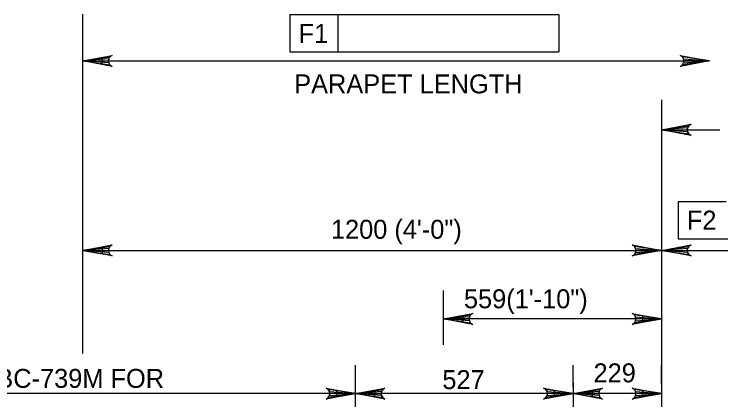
# Model space of a CAD drawing. Extents: x 0 to 36.3, y -66 to 0.
# Drawn here: x 4.419 to 8.89, y -11.865 to -9.424 of the extents above; entities that cross this region are included whole.
import ezdxf

# ---------------------------------------------------------------- set-up
doc = ezdxf.new("R2010")
doc.units = 0
doc.layers.add('3', color=7, linetype='Continuous')

msp = doc.modelspace()

# ---------------------------------------------------------------- linework, layer by layer
at = {"layer": '3'}
for p, q in [((4.8531, -11.5721), (4.8531, -9.4241)), ((6.1642, -9.4254), (6.4666, -9.4254)), ((6.1642, -9.4254), (6.1642, -9.6617)), ((6.4666, -9.4254), (6.4666, -9.6617)), ((6.4666, -9.4254), (7.8649, -9.4254)), ((7.8649, -9.4254), (7.8649, -9.6617)), ((6.1642, -9.6617), (7.8649, -9.6617)), ((4.8531, -9.72), (8.8184, -9.72)), ((8.5148, -9.9667), (8.5148, -16.3403)), ((8.5148, -10.1561), (8.8836, -10.1561)), ((8.6203, -10.6093), (8.9227, -10.6093)), ((8.6203, -10.6093), (8.6203, -10.8455)), ((8.6203, -10.8455), (10.0156, -10.8455)), ((4.8531, -10.9191), (8.5148, -10.9191)), ((8.5148, -10.9191), (13.045, -10.9191)), ((7.1347, -11.5162), (7.1347, -11.1725)), ((8.5148, -11.3525), (7.1347, -11.3525)), ((6.5788, -12.7536), (6.5788, -11.6451)), ((7.9551, -11.785), (7.9551, -11.6451)), ((8.5148, -11.7626), (8.5148, -11.6451)), ((7.955, -11.7564), (7.955, -12.3434)), ((6.5788, -11.8251), (3.0934, -11.8251)), ((7.9551, -11.8251), (6.5788, -11.8251)), ((8.5148, -11.8251), (7.9551, -11.8251))]:
    msp.add_line(p, q, dxfattribs=at)
for points in [[(4.8531, -9.72), (5.0395, -9.6851), (5.0252, -9.695), (5.0177, -9.7075), (5.0156, -9.72), (5.0177, -9.7325), (5.0252, -9.745), (5.0395, -9.7549), (4.8531, -9.72), (5.0252, -9.745), (5.0177, -9.7325), (4.8531, -9.72), (5.0156, -9.72), (5.0177, -9.7075), (4.8531, -9.72), (5.0252, -9.695)], [(8.8184, -9.72), (8.632, -9.7549), (8.6463, -9.745), (8.6538, -9.7325), (8.6559, -9.72), (8.6538, -9.7075), (8.6463, -9.695), (8.632, -9.6851), (8.8184, -9.72), (8.6463, -9.695), (8.6538, -9.7075), (8.8184, -9.72), (8.6559, -9.72), (8.6538, -9.7325), (8.8184, -9.72), (8.6463, -9.745)], [(8.5148, -10.1561), (8.7012, -10.1212), (8.6869, -10.1311), (8.6795, -10.1436), (8.6773, -10.1561), (8.6795, -10.1686), (8.6869, -10.1811), (8.7012, -10.191), (8.5148, -10.1561), (8.6869, -10.1811), (8.6795, -10.1686), (8.5148, -10.1561), (8.6773, -10.1561), (8.6795, -10.1436), (8.5148, -10.1561), (8.6869, -10.1311)], [(4.8531, -10.9191), (5.0395, -10.8842), (5.0252, -10.8941), (5.0177, -10.9066), (5.0156, -10.9191), (5.0177, -10.9316), (5.0252, -10.9441), (5.0395, -10.954), (4.8531, -10.9191), (5.0252, -10.9441), (5.0177, -10.9316), (4.8531, -10.9191), (5.0156, -10.9191), (5.0177, -10.9066), (4.8531, -10.9191), (5.0252, -10.8941)], [(8.5148, -10.9191), (8.3284, -10.954), (8.3428, -10.9441), (8.3502, -10.9316), (8.3523, -10.9191), (8.3502, -10.9066), (8.3428, -10.8941), (8.3284, -10.8842), (8.5148, -10.9191), (8.3428, -10.8941), (8.3502, -10.9066), (8.5148, -10.9191), (8.3523, -10.9191), (8.3502, -10.9316), (8.5148, -10.9191), (8.3428, -10.9441)], [(8.5148, -10.9191), (8.7012, -10.8842), (8.6869, -10.8941), (8.6795, -10.9066), (8.6773, -10.9191), (8.6795, -10.9316), (8.6869, -10.9441), (8.7012, -10.954), (8.5148, -10.9191), (8.6869, -10.9441), (8.6795, -10.9316), (8.5148, -10.9191), (8.6773, -10.9191), (8.6795, -10.9066), (8.5148, -10.9191), (8.6869, -10.8941)], [(7.1347, -11.3525), (7.3211, -11.3176), (7.3068, -11.3275), (7.2993, -11.34), (7.2972, -11.3525), (7.2993, -11.365), (7.3068, -11.3775), (7.3211, -11.3874), (7.1347, -11.3525), (7.3068, -11.3775), (7.2993, -11.365), (7.1347, -11.3525), (7.2972, -11.3525), (7.2993, -11.34), (7.1347, -11.3525), (7.3068, -11.3275)], [(8.5148, -11.3525), (8.3284, -11.3874), (8.3428, -11.3775), (8.3502, -11.365), (8.3523, -11.3525), (8.3502, -11.34), (8.3428, -11.3275), (8.3284, -11.3176), (8.5148, -11.3525), (8.3428, -11.3275), (8.3502, -11.34), (8.5148, -11.3525), (8.3523, -11.3525), (8.3502, -11.365), (8.5148, -11.3525), (8.3428, -11.3775)], [(6.5788, -11.8251), (6.3924, -11.86), (6.4067, -11.8501), (6.4142, -11.8376), (6.4163, -11.8251), (6.4142, -11.8126), (6.4067, -11.8001), (6.3924, -11.7902), (6.5788, -11.8251), (6.4067, -11.8001), (6.4142, -11.8126), (6.5788, -11.8251), (6.4163, -11.8251), (6.4142, -11.8376), (6.5788, -11.8251), (6.4067, -11.8501)], [(6.5788, -11.8251), (6.7652, -11.7902), (6.7509, -11.8001), (6.7435, -11.8126), (6.7413, -11.8251), (6.7435, -11.8376), (6.7509, -11.8501), (6.7652, -11.86), (6.5788, -11.8251), (6.7509, -11.8501), (6.7435, -11.8376), (6.5788, -11.8251), (6.7413, -11.8251), (6.7435, -11.8126), (6.5788, -11.8251), (6.7509, -11.8001)], [(7.9551, -11.8251), (7.7687, -11.86), (7.783, -11.8501), (7.7904, -11.8376), (7.7926, -11.8251), (7.7904, -11.8126), (7.783, -11.8001), (7.7687, -11.7902), (7.9551, -11.8251), (7.783, -11.8001), (7.7904, -11.8126), (7.9551, -11.8251), (7.7926, -11.8251), (7.7904, -11.8376), (7.9551, -11.8251), (7.783, -11.8501)], [(7.9551, -11.8251), (8.1415, -11.7902), (8.1272, -11.8001), (8.1197, -11.8126), (8.1176, -11.8251), (8.1197, -11.8376), (8.1272, -11.8501), (8.1415, -11.86), (7.9551, -11.8251), (8.1272, -11.8501), (8.1197, -11.8376), (7.9551, -11.8251), (8.1176, -11.8251), (8.1197, -11.8126), (7.9551, -11.8251), (8.1272, -11.8001)], [(8.5148, -11.8251), (8.3284, -11.86), (8.3428, -11.8501), (8.3502, -11.8376), (8.3523, -11.8251), (8.3502, -11.8126), (8.3428, -11.8001), (8.3284, -11.7902), (8.5148, -11.8251), (8.3428, -11.8001), (8.3502, -11.8126), (8.5148, -11.8251), (8.3523, -11.8251), (8.3502, -11.8376), (8.5148, -11.8251), (8.3428, -11.8501)]]:
    msp.add_lwpolyline(points, dxfattribs=at)
for points in [[(4.9731, -9.7), (4.9731, -9.74), (4.8531, -9.72)], [(4.9781, -10.9399), (4.9781, -10.8982), (4.8531, -10.9191)], [(7.2547, -11.3325), (7.2547, -11.3725), (7.1347, -11.3525)], [(8.3948, -11.3325), (8.3948, -11.3725), (8.5148, -11.3525)], [(6.4588, -11.8051), (6.4588, -11.8451), (6.5788, -11.8251)], [(6.6988, -11.8051), (6.6988, -11.8451), (6.5788, -11.8251)], [(7.8351, -11.8051), (7.8351, -11.8451), (7.9551, -11.8251)], [(8.0751, -11.8051), (8.0751, -11.8451), (7.9551, -11.8251)], [(8.3948, -11.8051), (8.3948, -11.8451), (8.5148, -11.8251)]]:
    msp.add_lwpolyline(points, close=True, dxfattribs=at)

# ---------------------------------------------------------------- texts
for s, p in [('F1', (6.2188, -9.6067)), ('F2', (8.6747, -10.7874))]:
    msp.add_text(s, height=0.12, rotation=359.9382, dxfattribs=at).set_placement(p)
for s, p in [('PARAPET LENGTH', (6.1908, -9.9255)), ('1200 (4\'-0")', (6.4231, -10.8453)), ('559(1\'-10")', (7.2645, -11.2852)), ('   REFER TO BC-739M FOR', (3.3169, -11.7888)), ('229', (8.0842, -11.7539)), ('527', (7.1279, -11.7967))]:
    msp.add_text(s, height=0.12, dxfattribs=at).set_placement(p)

doc.saveas('drawing.dxf')
